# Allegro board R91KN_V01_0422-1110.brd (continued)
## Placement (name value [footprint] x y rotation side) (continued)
U202  23E22387MNG8  [BGA0_8MM10X16-100]  135.76 42.81 180 top
U401  23E22387MNG8  [BGA0_8MM10X16-100]  135.76 73.78 0 top
U402  23E22387MNG8  [BGA0_8MM10X16-100]  135.76 73.78 180 bottom
U403  V_REG_FIX_4PIN  [DPAK_4PIN]  45.04 18.44 270 top
U601  APW7065  [SO8_1_78H]  63.69 102.34 270 top
U701  APW7065  [SO8_1_78H]  149.55 101.1 90 top
U851  uPI7701U8  [SO8_THERMAL_1_75H]  46.25 44.6 90 bottom
U861  uPI7701U8  [SO8_THERMAL_1_75H]  52.44 29.69 180 bottom
U1999  XX125  [SOP65X783-14]  30.45 29.9 180 bottom
U4001  LM96163CISD  [QFN050_10_3X3]  75.65 91.9 90 top
U4050  DS4402  [TDFN14_TH]  65.88 90.24 180 top
UNK+1.8V  TP_22mil_SM_top  [TS1206]  73.75 47.15 180 bottom
UNK+1V  TP_22mil_SM_top  [TS1206]  67.35 58.3 180 bottom
UNK+5V  TP_22mil_SM_top  [TS1206]  35.05 22.05 180 bottom
UNK+MVDD  TP_22mil_SM_top  [TS1206]  150.88 75.01 180 bottom
VDDC  TP_22mil_SM_top  [TS1206]  57.55 90.9 180 bottom
Y2  27.000MHz_10PPM  [XTAL_ABLS]  65.91 28.19 180 top
Y3  27.000MHz_10PPM_30R  [XTAL_NDK_NX3225DA]  69.11 72.14 0 bottom

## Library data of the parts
B2 B5-B9 B11 B12 B71 B72 B1502 B2505 MB9 = BEAD: User Part Number: 5050005600G; alternate symbols: (SMIND1005_0_5H_BGA)
B702 = BEAD: User Part Number: 5050003200G
B800 B801 B1500 B2503 = BEAD: User Part Number: 5050007300G
B850 = BEAD: User Part Number: 5200000200G; alternate symbols: (R0805)
B4001 = BEAD: User Part Number: 5050001900G
C3-C13 C15-C19 C22-C26 C28-C33 C36-C42 C53 C57 C59 C62 C66 C71 C75 C80 C86 C87 C90 C91 C149 C156 C163-C165 C167 C193 C1051 C1054 C1601-C1614 C1999 C2530-C2538 C2541 C4071 = CAP: User Part Number: 4171010400G; alternate symbols: (CAP1005_0_55H_BGA)
C14 C715 C716 = CAP: User Part Number: 4277010600G
C20 C21 C606 C633 C706 C718 = CAP: User Part Number: 4250015400G
C27 C58 C63 C68 C77 C78 C88 C89 C130-C133 C158 C196 C629 C630 C851 C852 C856 C861 C862 C866 C4001 MC174-MC177 = CAP: User Part Number: 4217010600G
C34 C61 C64 C67 C70 C73 C79 C85 C134-C140 C143-C146 C148 C150-C155 C161 C162 C168-C173 C179-C190 C194 C195 C295 C297 C800 C801 C841 C858 C868 C1052 C1055 C1501 C1504 C1507 C2510 C2513 C2516 C2722 C4002 C4013-C4015 C4020 = CAP: User Part Number: 4172010500G; alternate symbols: (CAP1005_0_55H_BGA)
C35 C74 C120-C124 C499 C500 C1050 C4400 = CAP: User Part Number: 4170010300G; alternate symbols: (CAP1005_BGA)
C43 C44 C47 C94 C95 C854 C864 C4100 C4401 C4402 = CAP: User Part Number: 4172010400G; alternate symbols: (CAP1005_BGA,CAP1005_TRACE)
C82 C83 C92 C93 C1004-C1008 C2004-C2006 = CAP: User Part Number: 4170001200G; alternate symbols: (CAP1005_BGA)
C125-C129 C141 C142 C355-C363 C370-C377 C413 C438 C448 C463 C486-C489 C623 C725 C846 C1502 C1505 C1508 C2511 C2514 C2517 = CAP: User Part Number: 4170010400G; alternate symbols: (CAP1005_0_55H_BGA,CAP1005_0_55H_BGA_B)
C147 C174-C177 C1500 C1503 C1506 C2509 C2512 C2515 C4070 MC130-MC133 MC196 MC364-MC369 MC378-MC383 = CAP: User Part Number: 4250047500G
C300-C354 C384-C386 = CAP: User Part Number: 4170010500G; alternate symbols: (CAP1005_BGA)
C364-C369 C378-C383 C2540 = CAP: User Part Number: 4210010600G; alternate symbols: (CAP2012_1_53H_VIA)
C410 = CAP: User Part Number: *
C411 = CAP: User Part Number: *; alternate symbols: (CAP1005_BGA)
C603 C703 = CAP: User Part Number: 4210022400G
C605 C705 = CAP: User Part Number: 4240010400G
C608 = CAP: User Part Number: 4253010500G
C609 C615-C617 C619-C621 = CAP: User Part Number: 4225010600G; alternate symbols: (CAP3216_O)
C611 C624 C711 C727 = CAP: User Part Number: 4170015300G; alternate symbols: (CAP1005_BGA)
C612 C712 = CAP: User Part Number: 4170015100G; alternate symbols: (CAP1005_BGA)
C613 C713 = CAP: User Part Number: 4170039200G; alternate symbols: (CAP1005_BGA)
C625 C626 = CAP_POL#1: User Part Number: 4053082709G
C631 = CAP_POL: User Part Number: 4053027702G
C708 = CAP: User Part Number: 4171010300G; alternate symbols: (CAP1005_BGA)
C717 C719 = CAP: User Part Number: 4211047500G
C723 C724 = CAP: User Part Number: 4220010600G
C726 C729 = CAP_POL: User Part Number: 4053082700G
C728 = CAP: User Part Number: 4250039100G
C730 = CAP_POL: User Part Number: 4053010700G
C843 = CAP: User Part Number: 4173010400G; alternate symbols: (CAP1005_BGA)
C855 C865 = CAP: User Part Number: 4170033000G; alternate symbols: (CAP1005_BGA)
C1001-C1003 C2001-C2003 = CAP: User Part Number: 417008R000G; alternate symbols: (CAP1005_BGA)
C1010 = CAP: User Part Number: 4250068000G
C1011 = CAP: User Part Number: 4250010500G
C1624 = CAP: User Part Number: 4240010500G
C3600 C3608 = CAP: User Part Number: 4170068000G; alternate symbols: (CAP1005_BGA)
C4003 = CAP: User Part Number: 4170010100G; alternate symbols: (CAP1005_BGA)
C4004 = CAP: User Part Number: 4170022200G; alternate symbols: (CAP1005_BGA)
C4008 = CAP: User Part Number: 4210010500G
C4102 = CAP: User Part Number: 4213010500G
C4103 = CAP: User Part Number: 4252010500G
C4403-C4410 = CAP#1: User Part Number: 4171010400G; alternate symbols: (C0402,CAP1005_0_55H_BGA)
D601 D701 D4100 = SCHOTTKY: User Part Number: 5170005600G
D1000-D1002 D2500-D2502 D4403-D4406 = DIODE: User Part Number: 5150004000G
D1003-D1006 = DIODE: User Part Number: 5150004100G
D1600-D1603 D2503 D2504 D4401 D4402 = RCLAMP0524P: User Part Number: 5150003200G
D4000 = LED: User Part Number: 2510002300G
D4400 = DIODE_SERIES: User Part Number: 5170005400G
F400 = FUSE: User Part Number: *
F2501 = FUSE: User Part Number: 5120003100G
HS2 = HEATSINK_WVIA: User Part Number: 7120181000G
J1601 = DVI_6SH: User Part Number: 6140034304G
J2501 = 6140054500G: User Part Number: *
J4004 = CON08: User Part Number: 6020021700G
JU4001 = CON02: User Part Number: 6010007800G
L601 L701 = INDUCTOR POL: User Part Number: *
L611 = IND_POL: User Part Number: 5260054400G
L1001-L1003 L2001-L2003 = IND: User Part Number: 5260033700G
MJ1001 = VGA: User Part Number: 6052003000G
MJ2501 = 6140059200G: User Part Number: *
MPCIE1 = EDGECON_PCIE_164P: User Part Number: 614NOPN084
MR43-MR47 MR50-MR58 MR1240 MR1241 R24 R32 R43-R47 R50-R58 R63 R225 R227 R229 R230 R844 R849 R859 R862 R863 R1240 R1241 R1617 R1618 R2527 R2530 R3600 R4011 R4045 R4101 R4409 R4410 = RES: User Part Number: 3150010300G; alternate symbols: (RES1005_BGA)
MR48 MR49 R7 R35 R37-R39 R48 R49 R59 R60 R436 R4044 R4051 R4054 R4057 R4058 R4060 R4102 R4105 R4106 R4408 = RES: User Part Number: 3150010200G; alternate symbols: (RES1005_BGA)
MR70 MR71 R70 R71 R843 R845 R846 R4040 R4046 R4112 = RES: User Part Number: 3150051200G; alternate symbols: (RES1005_BGA)
MR75 R75 = RES: User Part Number: 3160182000G; alternate symbols: (RES1005_BGA)
MR850 R595 R4110 = RES: User Part Number: 3210000000G
MR858 = RES: User Part Number: 3180004100G
MR870-MR873 = RES: User Part Number: 322003R300G
MR1015-MR1019 MR1027-MR1029 R1015-R1019 = RES#1: User Part Number: 3150000000G; alternate symbols: (RES1005_BGA,RES1005_TRACE)
MR2014 MR2721 MR4076 NR75 R3 R4 R30 R36 R61 R65 R72-R74 R226 R228 R596 R597 R609 R614 R621 R709 R714 R721 R839 R856 R866 R2014 R2721 R3616 R4050 R4052 R4062 R4065 R4076-R4078 R4080 R4406 TR75 = RES: User Part Number: 3150000000G; alternate symbols: (RES1005_BGA,RES1005_TRACE)
MT200 = MOUNTING_8PINS: User Part Number: 620NOPN029
MU861 = UP7706: User Part Number: 2480086700G
NOREF#4 NOREF#13 NOREF#17 NOREF#19 NOREF#20 NOREF#24 NOREF#26 NOREF#31 NOREF#37 NOREF#41 = -: User Part Number: *
NR4000 R1005 R1008 R2005 R2008 R2701 R2703 = RES: User Part Number: 3150022200G; alternate symbols: (RES1005_BGA)
NS600 NS700 = NET_SHORT: User Part Number: 620NOPN018; alternate symbols: (NET_SHORT_0_50,NET_SHORT_SMT,NET_SHORT_SMT_0M20)
Q1 Q2 Q1200 Q1201 = MOS_N: User Part Number: 2020000600G; alternate symbols: (SOT23_3PIN_1_143H_ALT)
Q601 Q603 Q701 Q703 = MOS_N_4D_3S_TH: User Part Number: *
Q840-Q842 Q850-Q852 Q1602 Q2513 Q4006 Q4007 Q4009-Q4011 Q4013 Q4016 Q4050 Q4100 Q4401 Q4402 = NPN: User Part Number: 2021390400G
Q1601 Q2701 Q4014 = MOS_N: User Part Number: 2020002300G
Q1801 Q1802 Q1804 = MOS_N: User Part Number: *
Q1803 = NPN: User Part Number: *
Q4008 Q4101 Q4102 Q4400 = PNP: User Part Number: 2021390600G
Q4103 = NPN_2C: User Part Number: 2020030300G
R1 R2 = RES: User Part Number: 3160453200G; alternate symbols: (RES1005_BGA)
R8 = RES: User Part Number: 3160200100G; alternate symbols: (RES1005_BGA,R0402)
R9 = RES: User Part Number: 3160127100G; alternate symbols: (RES1005_BGA)
R12 R1601-R1614 R2713-R2720 R4059 = RES: User Part Number: 3160499000G; alternate symbols: (RES1005_BGA)
R13-R16 R1006 R1009 R2006 R2009 R4081 = RES: User Part Number: 3150033000G; alternate symbols: (RES1005_BGA)
R21 R76 = RES: User Part Number: 3160221000G; alternate symbols: (RES1005_BGA)
R22 = RES: User Part Number: 3160110000G; alternate symbols: (RES1005_BGA)
R23 = RES: User Part Number: 3160715000G; alternate symbols: (RES1005_BGA)
R31 = RES: User Part Number: 3160100400G; alternate symbols: (RES1005_BGA)
R33 R34 R4017 R4018 = RES: User Part Number: 3150047200G; alternate symbols: (RES1005_0_4H_BGA)
R201-R216 R611 R711 = RES: User Part Number: 3160499100G; alternate symbols: (RES1005_BGA)
R217-R220 R301-R303 = RES: User Part Number: 3160243000G; alternate symbols: (RES1005_BGA)
R221-R224 = RES: User Part Number: 3150056000G; alternate symbols: (RES1005_BGA)
R291-R294 R4001 R4002 = RES: User Part Number: 3160100000G; alternate symbols: (RES1005_0_4H_BGA)
R296 R297 = RES: User Part Number: 316051R100G; alternate symbols: (RES1005_BGA)
R298 R1500 R2500 = RES: User Part Number: 3160150000G; alternate symbols: (RES1005_BGA,RES1005_BGA_B)
R600 R622 R700 R722 = RES: User Part Number: 3230000000G
R607 R707 = RES: User Part Number: 321002R200G
R608 R616 R702 R860 R880 = RES: User Part Number: 3220000000G
R610 R1225 = RES: User Part Number: 3160787200G; alternate symbols: (RES1005_BGA)
R612 R712 = RES: User Part Number: 3160294100G; alternate symbols: (RES1005_BGA)
R613 R713 = RES: User Part Number: 3160365100G; alternate symbols: (RES1005_BGA)
R615 R715 = RES: User Part Number: 3160422200G; alternate symbols: (RES1005_BGA)
R619 = RES: User Part Number: 3210030100G
R710 = RES: User Part Number: 3160105200G
R719 R4411-R4413 = RES: User Part Number: 321001R000G
R841 = RES: User Part Number: 3160475100G; alternate symbols: (RES1005_BGA)
R850 = RES: User Part Number: 3160232100G
R851 R853 R4039 R4111 = RES: User Part Number: 3160100100G; alternate symbols: (RES1005_BGA)
R852 = RES: User Part Number: 3160113200G; alternate symbols: (RES1005_BGA)
R854 R857 R864 = RES: User Part Number: 3160100200G; alternate symbols: (RES1005_BGA)
R855 = RES: User Part Number: 3160267100G; alternate symbols: (RES1005_BGA)
R858 = RES: User Part Number: 3180002100G
R865 = RES: User Part Number: 3160130200G; alternate symbols: (RES1005_BGA)
R870-R873 = RES: User Part Number: 3180006800G
R1001-R1003 R2001-R2003 = RES: User Part Number: 316075R000G; alternate symbols: (RES1005_BGA)
R1010 R1011 = RES: User Part Number: 3150010000G; alternate symbols: (RES1005_BGA)
R1027-R1029 R2027-R2029 = RES: User Part Number: 316037R400G; alternate symbols: (RES1005_BGA)
R1226 = RES: User Part Number: 3160165300G
R1804 R1805 = RES: User Part Number: *; alternate symbols: (RES1005_BGA,R0402)
R2522 R2523 R4047 R4053 R4063 R4403 = RES: User Part Number: 3150010400G; alternate symbols: (RES1005_BGA)
R2524 R2526 R4108 = RES: User Part Number: 3150010500G; alternate symbols: (RES1005_BGA)
R3615 = RES: User Part Number: 3150068100G; alternate symbols: (RES1005_BGA)
R4038 = RES: User Part Number: 3160220100G
R4043 = RES: User Part Number: 3150047400G; alternate symbols: (RES1005_BGA)
R4055 R4061 R4404 R4405 R4407 = RES: User Part Number: 3150020300G; alternate symbols: (RES1005_BGA)
R4056 = RES: User Part Number: 315003R900G
R4070 R4071 = RES: User Part Number: 3150020100G; alternate symbols: (RES1005_BGA)
R4072 R4073 = RES: User Part Number: 3150030400G; alternate symbols: (RES1005_BGA)
R4075 = RES: User Part Number: 315001R800G; alternate symbols: (RES1005_BGA)
R4100 = RES: User Part Number: 3160261100G; alternate symbols: (RES1005_BGA)
R4103 = RES: User Part Number: 3150022300G; alternate symbols: (RES1005_BGA)
R4107 = RES: User Part Number: 3150082100G; alternate symbols: (RES1005_BGA)
R4113 = RES: User Part Number: 3150068200G; alternate symbols: (RES1005_BGA)
R4400-R4402 = RES: User Part Number: 3150047300G; alternate symbols: (RES1005_BGA)
SW4001 SW4002 = SPST: User Part Number: 5030003000G
TP58 TP59 TP91 TP94 TP97 TP101-TP123 TP500-TP503 TP1700 = TEST_POINT: User Part Number: 620NOPN000; alternate symbols: (TP07X025,TP055PRI,TP056X025,TP050,TP051X025,TP050X025,TP1_00PRI,TPVIA0_5-0_9SEC,TPVIA0_6-0_9SEC,TPVIA0_9-0_9SEC,TPVIA0_5-0_7SEC,TPSMT0_9PRI,TPSMT0_7PRI,TP089X070,TP0_127SQ_PRI,TPSMT0_7PRI)
U1 = CAICOS_DDR3: User Part Number: 215-0804000-00
U2 = SERIAL_FLASH: User Part Number: 2280007900G; alternate symbols: (SO8_1_78H_ALT)
U4 = XX08: User Part Number: 2430002900G
U12 = SL16010DCT: User Part Number: 2750013000G
U201 U202 U401 U402 = DDR3_64MX16_23E22387MNG8: alternate symbols: (BGA0_8MM10X16-100_HYNIX)
U403 = V_REG_FIX_4PIN: User Part Number: *
U601 U701 = APW7065: User Part Number: 2480059700G
U851 U861 = 2480063100G_UP7701: User Part Number: 2480063100G
U1999 = XX125: User Part Number: 2430008702G
U4001 = LM96163: User Part Number: 2480086000G
U4050 = DS4402: User Part Number: 2800006000G
UNK+1.8V UNK+1V UNK+5V UNK+MVDD VDDC = 620NOPN008: User Part Number: *
Y2 = CRYSTAL: User Part Number: 5028270002G
Y3 = CRYSTAL_4P_NC: User Part Number: 502G270000G

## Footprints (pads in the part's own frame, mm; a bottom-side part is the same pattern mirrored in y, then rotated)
BGA0_8MM10X16-100
  round 0.356 smd: (-4,6) (-4,-6) (4,6) (4,-6) A1(-3.2,6) A2(-2.4,6) A3(-1.6,6) A7(1.6,6) A8(2.4,6) A9(3.2,6) B1(-3.2,5.2) B2(-2.4,5.2) B3(-1.6,5.2) B7(1.6,5.2) B8(2.4,5.2) B9(3.2,5.2) C1(-3.2,4.4) C2(-2.4,4.4) C3(-1.6,4.4) C7(1.6,4.4) C8(2.4,4.4) C9(3.2,4.4) D1(-3.2,3.6) D2(-2.4,3.6) D3(-1.6,3.6) D7(1.6,3.6) D8(2.4,3.6) D9(3.2,3.6) E1(-3.2,2.8) E2(-2.4,2.8) E3(-1.6,2.8) E7(1.6,2.8) E8(2.4,2.8) E9(3.2,2.8) F1(-3.2,2) F2(-2.4,2) F3(-1.6,2) F7(1.6,2) F8(2.4,2) F9(3.2,2) G1(-3.2,1.2) G2(-2.4,1.2) G3(-1.6,1.2) G7(1.6,1.2) G8(2.4,1.2) G9(3.2,1.2) H1(-3.2,0.4) H2(-2.4,0.4) H3(-1.6,0.4) H7(1.6,0.4) H8(2.4,0.4) H9(3.2,0.4) J1(-3.2,-0.4) J2(-2.4,-0.4) J3(-1.6,-0.4) J7(1.6,-0.4) J8(2.4,-0.4) J9(3.2,-0.4) K1(-3.2,-1.2) K2(-2.4,-1.2) K3(-1.6,-1.2) K7(1.6,-1.2) K8(2.4,-1.2) K9(3.2,-1.2) L1(-3.2,-2) L2(-2.4,-2) L3(-1.6,-2) L7(1.6,-2) L8(2.4,-2) L9(3.2,-2) M1(-3.2,-2.8) M2(-2.4,-2.8) M3(-1.6,-2.8) M7(1.6,-2.8) M8(2.4,-2.8) M9(3.2,-2.8) N1(-3.2,-3.6) N2(-2.4,-3.6) N3(-1.6,-3.6) N7(1.6,-3.6) N8(2.4,-3.6) N9(3.2,-3.6) P1(-3.2,-4.4) P2(-2.4,-4.4) P3(-1.6,-4.4) P7(1.6,-4.4) P8(2.4,-4.4) P9(3.2,-4.4) R1(-3.2,-5.2) R2(-2.4,-5.2) R3(-1.6,-5.2) R7(1.6,-5.2) R8(2.4,-5.2) R9(3.2,-5.2) T1(-3.2,-6) T2(-2.4,-6) T3(-1.6,-6) T7(1.6,-6) T8(2.4,-6) T9(3.2,-6)
BGA0_8X1_0MM23X23-631
  round 0.406 smd: A3(-10,10.8) A30(10,10.8) A32(10.8,10.8) AB7(-7.6,-4.2) AB8(-6.8,-4.2) AB9(-6,-4.2) AB10(-5.2,-4.2) AB23(5.2,-4.2) AB24(6,-4.2) AB25(6.8,-4.2) AB26(7.6,-4.2) AC11(-4.2,-5.2) AC13(-3,-5.2) AC14(-1.8,-5.2) AC16(-0.6,-5.2) AC17(0.6,-5.2) AC19(1.8,-5.2) AC20(3,-5.2) AC22(4.2,-5.2) AD11(-4.2,-6) AD13(-3,-6) AD14(-1.8,-6) AD16(-0.6,-6) AD17(0.6,-6) AD19(1.8,-6) AD20(3,-6) AD22(4.2,-6) AE11(-4.2,-6.8) AE13(-3,-6.8) AE14(-1.8,-6.8) AE16(-0.6,-6.8) AE17(0.6,-6.8) AE19(1.8,-6.8) AE20(3,-6.8) AE22(4.2,-6.8) AF11(-4.2,-7.6) AF13(-3,-7.6) AF14(-1.8,-7.6) AF16(-0.6,-7.6) AF17(0.6,-7.6) AF19(1.8,-7.6) AF20(3,-7.6) AF22(4.2,-7.6) AK1(-10.8,-10) AK3(-10,-10) AK30(10,-10) AK32(10.8,-10) AM1(-10.8,-10.8) AM3(-10,-10.8) AM30(10,-10.8) AM32(10.8,-10.8) C1(-10.8,10) C3(-10,10) C30(10,10) C32(10.8,10) G11(-4.2,7.6) G13(-3,7.6) G14(-1.8,7.6) G16(-0.6,7.6) G17(0.6,7.6) G19(1.8,7.6) G20(3,7.6) G22(4.2,7.6) H11(-4.2,6.8) H13(-3,6.8) H14(-1.8,6.8) H16(-0.6,6.8) H17(0.6,6.8) H19(1.8,6.8) H20(3,6.8) H22(4.2,6.8) J11(-4.2,6) J13(-3,6) J14(-1.8,6) J16(-0.6,6) J17(0.6,6) J19(1.8,6) J20(3,6) J22(4.2,6) K11(-4.2,5.2) K13(-3,5.2) K14(-1.8,5.2) K16(-0.6,5.2) K17(0.6,5.2) K19(1.8,5.2) K20(3,5.2) K22(4.2,5.2) L7(-7.6,4.2) L8(-6.8,4.2) L9(-6,4.2) L10(-5.2,4.2) L23(5.2,4.2) L24(6,4.2) L25(6.8,4.2) L26(7.6,4.2) N7(-7.6,3) N8(-6.8,3) N9(-6,3) N10(-5.2,3) N23(5.2,3) N24(6,3) N25(6.8,3) N26(7.6,3) P7(-7.6,1.8) P8(-6.8,1.8) P9(-6,1.8) P10(-5.2,1.8) P23(5.2,1.8) P24(6,1.8) P25(6.8,1.8) P26(7.6,1.8) T7(-7.6,0.6) T8(-6.8,0.6) T9(-6,0.6) T10(-5.2,0.6) T23(5.2,0.6) T24(6,0.6) T25(6.8,0.6) T26(7.6,0.6) U7(-7.6,-0.6) U8(-6.8,-0.6) U9(-6,-0.6) U10(-5.2,-0.6) U23(5.2,-0.6) U24(6,-0.6) U25(6.8,-0.6) U26(7.6,-0.6) W7(-7.6,-1.8) W8(-6.8,-1.8) W9(-6,-1.8) W10(-5.2,-1.8) W23(5.2,-1.8) W24(6,-1.8) W25(6.8,-1.8) W26(7.6,-1.8) Y7(-7.6,-3) Y8(-6.8,-3) Y9(-6,-3) Y10(-5.2,-3) Y23(5.2,-3) Y24(6,-3) Y25(6.8,-3) Y26(7.6,-3)
  round 0.3 smd: A5(-9.2,10.8) A7(-7.6,10.8) A9(-6,10.8) A11(-4.4,10.8) A13(-2.8,10.8) A15(-1.2,10.8) A17(0.4,10.8) A19(2,10.8) A21(3.6,10.8) A23(5.2,10.8) A25(6.8,10.8) A27(8.4,10.8) A28(9.2,10.8) AA1(-10.8,-3.6) AA3(-10,-3.6) AA5(-9.2,-3.6) AA6(-8.4,-3.6) AA27(8.4,-3.6) AA29(9.6,-3.6) AA31(10.4,-3.6) AB2(-10.4,-4.4) AB4(-9.6,-4.4) AB6(-8.4,-4.4) AB27(8.4,-4.4) AB28(9.2,-4.4) AB30(10,-4.4) AB32(10.8,-4.4) AC1(-10.8,-5.2) AC3(-10,-5.2) AC5(-9.2,-5.2) AC6(-8.4,-5.2) AC7(-7.6,-5.2) AC8(-6.8,-5.2) AC9(-6,-5.2) AC10(-5.2,-5.2) AC23(5.2,-5.2) AC24(6,-5.2) AC25(6.8,-5.2) AC26(7.6,-5.2) AC27(8.4,-5.2) AC29(9.6,-5.2) AC31(10.4,-5.2) AD2(-10.4,-6) AD4(-9.6,-6) AD6(-8.4,-6) AD7(-7.6,-6) AD8(-6.8,-6) AD9(-6,-6) AD10(-5.2,-6) AD23(5.2,-6) AD24(6,-6) AD25(6.8,-6) AD26(7.6,-6) AD27(8.4,-6) AD28(9.2,-6) AD30(10,-6) AD32(10.8,-6) AE1(-10.8,-6.8) AE3(-10,-6.8) AE5(-9.2,-6.8) AE6(-8.4,-6.8) AE7(-7.6,-6.8) AE8(-6.8,-6.8) AE9(-6,-6.8) AE10(-5.2,-6.8) AE23(5.2,-6.8) AE24(6,-6.8) AE25(6.8,-6.8) AE26(7.6,-6.8) AE27(8.4,-6.8) AE29(9.6,-6.8) AE31(10.4,-6.8) AF2(-10.4,-7.6) AF4(-9.6,-7.6) AF6(-8.4,-7.6) AF7(-7.6,-7.6) AF8(-6.8,-7.6) AF9(-6,-7.6) AF10(-5.2,-7.6) AF23(5.2,-7.6) AF24(6,-7.6) AF25(6.8,-7.6) AF26(7.6,-7.6) AF27(8.4,-7.6) AF28(9.2,-7.6) AF30(10,-7.6) AF32(10.8,-7.6) AG1(-10.8,-8.4) AG3(-10,-8.4) AG5(-9.2,-8.4) AG6(-8.4,-8.4) AG7(-7.6,-8.4) AG8(-6.8,-8.4) AG9(-6,-8.4) AG10(-5.2,-8.4) AG11(-4.4,-8.4) AG12(-3.6,-8.4) AG13(-2.8,-8.4) AG14(-2,-8.4) AG15(-1.2,-8.4) AG16(-0.4,-8.4) AG17(0.4,-8.4) AG18(1.2,-8.4) AG19(2,-8.4) AG20(2.8,-8.4) AG21(3.6,-8.4) AG22(4.4,-8.4) AG23(5.2,-8.4) AG24(6,-8.4) AG25(6.8,-8.4) AG26(7.6,-8.4) AG27(8.4,-8.4) AG29(9.6,-8.4) AG31(10.4,-8.4) AH1(-10.8,-9.2) AH3(-10,-9.2) AH5(-9.2,-9.2) AH6(-8.4,-9.2) AH8(-6.8,-9.2) AH10(-5.2,-9.2) AH12(-3.6,-9.2) AH14(-2,-9.2) AH16(-0.4,-9.2) AH18(1.2,-9.2) AH20(2.8,-9.2) AH22(4.4,-9.2) AH24(6,-9.2) AH26(7.6,-9.2) AH28(9.2,-9.2) AH30(10,-9.2) AH32(10.8,-9.2) AJ7(-7.6,-9.6) AJ9(-6,-9.6) AJ11(-4.4,-9.6) AJ13(-2.8,-9.6) AJ15(-1.2,-9.6) AJ17(0.4,-9.6) AJ19(2,-9.6) AJ21(3.6,-9.6) AJ23(5.2,-9.6) AJ25(6.8,-9.6) AJ27(8.4,-9.6) AK5(-9.2,-10) AK6(-8.4,-10) AK8(-6.8,-10) AK10(-5.2,-10) AK12(-3.6,-10) AK14(-2,-10) AK16(-0.4,-10) AK18(1.2,-10) AK20(2.8,-10) AK22(4.4,-10) AK24(6,-10) AK26(7.6,-10) AK28(9.2,-10) AL7(-7.6,-10.4) AL9(-6,-10.4) AL11(-4.4,-10.4) AL13(-2.8,-10.4) AL15(-1.2,-10.4) AL17(0.4,-10.4) AL19(2,-10.4) AL21(3.6,-10.4) AL23(5.2,-10.4) AL25(6.8,-10.4) AL27(8.4,-10.4) AM5(-9.2,-10.8) AM6(-8.4,-10.8) AM8(-6.8,-10.8) AM10(-5.2,-10.8) AM12(-3.6,-10.8) AM14(-2,-10.8) AM16(-0.4,-10.8) AM18(1.2,-10.8) AM20(2.8,-10.8) AM22(4.4,-10.8) AM24(6,-10.8) AM26(7.6,-10.8) AM28(9.2,-10.8) B6(-8.4,10.4) B8(-6.8,10.4) B10(-5.2,10.4) B12(-3.6,10.4) B14(-2,10.4) B16(-0.4,10.4) B18(1.2,10.4) B20(2.8,10.4) B22(4.4,10.4) B24(6,10.4) B26(7.6,10.4) C5(-9.2,10) C7(-7.6,10) C9(-6,10) C11(-4.4,10) C13(-2.8,10) C15(-1.2,10) C17(0.4,10) C19(2,10) C21(3.6,10) C23(5.2,10) C25(6.8,10) C27(8.4,10) C28(9.2,10) D6(-8.4,9.6) D8(-6.8,9.6) D10(-5.2,9.6) D12(-3.6,9.6) D14(-2,9.6) D16(-0.4,9.6) D18(1.2,9.6) D20(2.8,9.6) D22(4.4,9.6) D24(6,9.6) D26(7.6,9.6) E1(-10.8,9.2) E3(-10,9.2) E5(-9.2,9.2) E7(-7.6,9.2) E9(-6,9.2) E11(-4.4,9.2) E13(-2.8,9.2) E15(-1.2,9.2) E17(0.4,9.2) E19(2,9.2) E21(3.6,9.2) E23(5.2,9.2) E25(6.8,9.2) E27(8.4,9.2) E28(9.2,9.2) E30(10,9.2) E32(10.8,9.2) F2(-10.4,8.4) F4(-9.6,8.4) F6(-8.4,8.4) F7(-7.6,8.4) F8(-6.8,8.4) F9(-6,8.4) F10(-5.2,8.4) F11(-4.4,8.4) F12(-3.6,8.4) F13(-2.8,8.4) F14(-2,8.4) F15(-1.2,8.4) F16(-0.4,8.4) F17(0.4,8.4) F18(1.2,8.4) F19(2,8.4) F20(2.8,8.4) F21(3.6,8.4) F22(4.4,8.4) F23(5.2,8.4) F24(6,8.4) F25(6.8,8.4) F26(7.6,8.4) F27(8.4,8.4) F28(9.2,8.4) F30(10,8.4) F32(10.8,8.4) G1(-10.8,7.6) G3(-10,7.6) G5(-9.2,7.6) G6(-8.4,7.6) G7(-7.6,7.6) G8(-6.8,7.6) G9(-6,7.6) G10(-5.2,7.6) G23(5.2,7.6) G24(6,7.6) G25(6.8,7.6) G26(7.6,7.6) G27(8.4,7.6) G29(9.6,7.6) G31(10.4,7.6) H2(-10.4,6.8) H4(-9.6,6.8) H6(-8.4,6.8) H7(-7.6,6.8) H8(-6.8,6.8) H9(-6,6.8) H10(-5.2,6.8) H23(5.2,6.8) H24(6,6.8) H25(6.8,6.8) H26(7.6,6.8) H27(8.4,6.8) H28(9.2,6.8) H30(10,6.8) H32(10.8,6.8) J1(-10.8,6) J3(-10,6) J5(-9.2,6) J6(-8.4,6) J7(-7.6,6) J8(-6.8,6) J9(-6,6) J10(-5.2,6) J23(5.2,6) J24(6,6) J25(6.8,6) J26(7.6,6) J27(8.4,6) J29(9.6,6) J31(10.4,6) K2(-10.4,5.2) K4(-9.6,5.2) K6(-8.4,5.2) K7(-7.6,5.2) K8(-6.8,5.2) K9(-6,5.2) K10(-5.2,5.2) K23(5.2,5.2) K24(6,5.2) K25(6.8,5.2) K26(7.6,5.2) K27(8.4,5.2) K28(9.2,5.2) K30(10,5.2) K32(10.8,5.2) L1(-10.8,4.4) L3(-10,4.4) L5(-9.2,4.4) L6(-8.4,4.4) L27(8.4,4.4) L29(9.6,4.4) L31(10.4,4.4) M2(-10.4,3.6) M4(-9.6,3.6) M6(-8.4,3.6) M27(8.4,3.6) M28(9.2,3.6) M30(10,3.6) M32(10.8,3.6) N1(-10.8,2.8) N3(-10,2.8) N5(-9.2,2.8) N6(-8.4,2.8) N27(8.4,2.8) N29(9.6,2.8) N31(10.4,2.8) P2(-10.4,2) P4(-9.6,2) P6(-8.4,2) P27(8.4,2) P28(9.2,2) P30(10,2) P32(10.8,2) R1(-10.8,1.2) R3(-10,1.2) R5(-9.2,1.2) R6(-8.4,1.2) R27(8.4,1.2) R29(9.6,1.2) R31(10.4,1.2) T2(-10.4,0.4) T4(-9.6,0.4) T6(-8.4,0.4) T27(8.4,0.4) T28(9.2,0.4) T30(10,0.4) T32(10.8,0.4) U1(-10.8,-0.4) U3(-10,-0.4) U5(-9.2,-0.4) U6(-8.4,-0.4) U27(8.4,-0.4) U29(9.6,-0.4) U31(10.4,-0.4) V2(-10.4,-1.2) V4(-9.6,-1.2) V6(-8.4,-1.2) V27(8.4,-1.2) V28(9.2,-1.2) V30(10,-1.2) V32(10.8,-1.2) W1(-10.8,-2) W3(-10,-2) W5(-9.2,-2) W6(-8.4,-2) W27(8.4,-2) W29(9.6,-2) W31(10.4,-2) Y2(-10.4,-2.8) Y4(-9.6,-2.8) Y6(-8.4,-2.8) Y27(8.4,-2.8) Y28(9.2,-2.8) Y30(10,-2.8) Y32(10.8,-2.8)
  round 0.5 smd: AA11(-4.4,-3.4) AA12(-3.4,-3.4) AA13(-2.4,-3.4) AA15(-1.4,-3.4) AA16(-0.4,-3.4) AA17(0.4,-3.4) AA18(1.4,-3.4) AA20(2.4,-3.4) AA21(3.4,-3.4) AA22(4.4,-3.4) AB11(-4.4,-4.4) AB12(-3.4,-4.4) AB13(-2.4,-4.4) AB15(-1.4,-4.4) AB16(-0.4,-4.4) AB17(0.4,-4.4) AB18(1.4,-4.4) AB20(2.4,-4.4) AB21(3.4,-4.4) AB22(4.4,-4.4) L11(-4.4,4.4) L12(-3.4,4.4) L13(-2.4,4.4) L15(-1.4,4.4) L16(-0.4,4.4) L17(0.4,4.4) L18(1.4,4.4) L20(2.4,4.4) L21(3.4,4.4) L22(4.4,4.4) M11(-4.4,3.4) M12(-3.4,3.4) M13(-2.4,3.4) M15(-1.4,3.4) M16(-0.4,3.4) M17(0.4,3.4) M18(1.4,3.4) M20(2.4,3.4) M21(3.4,3.4) M22(4.4,3.4) N11(-4.4,2.4) N12(-3.4,2.4) N13(-2.4,2.4) N15(-1.4,2.4) N16(-0.4,2.4) N17(0.4,2.4) N18(1.4,2.4) N20(2.4,2.4) N21(3.4,2.4) N22(4.4,2.4) R11(-4.4,1.4) R12(-3.4,1.4) R13(-2.4,1.4) R15(-1.4,1.4) R16(-0.4,1.4) R17(0.4,1.4) R18(1.4,1.4) R20(2.4,1.4) R21(3.4,1.4) R22(4.4,1.4) T11(-4.4,0.4) T12(-3.4,0.4) T13(-2.4,0.4) T15(-1.4,0.4) T16(-0.4,0.4) T17(0.4,0.4) T18(1.4,0.4) T20(2.4,0.4) T21(3.4,0.4) T22(4.4,0.4) U11(-4.4,-0.4) U12(-3.4,-0.4) U13(-2.4,-0.4) U15(-1.4,-0.4) U16(-0.4,-0.4) U17(0.4,-0.4) U18(1.4,-0.4) U20(2.4,-0.4) U21(3.4,-0.4) U22(4.4,-0.4) V11(-4.4,-1.4) V12(-3.4,-1.4) V13(-2.4,-1.4) V15(-1.4,-1.4) V16(-0.4,-1.4) V17(0.4,-1.4) V18(1.4,-1.4) V20(2.4,-1.4) V21(3.4,-1.4) V22(4.4,-1.4) Y11(-4.4,-2.4) Y12(-3.4,-2.4) Y13(-2.4,-2.4) Y15(-1.4,-2.4) Y16(-0.4,-2.4) Y17(0.4,-2.4) Y18(1.4,-2.4) Y20(2.4,-2.4) Y21(3.4,-2.4) Y22(4.4,-2.4)
CAP254X635_8_26H
  rect 1.397x1.397 hole 1: 1(-1.27,0)
  round 1.397 hole 1: 2(1.27,0)
CAP1005
  custom 0.138x0.138 smd: 1(0,0.493) 2(0,-0.493)
CAP1005_0_55H
  custom 0.138x0.138 smd: 1(0,0.493) 2(0,-0.493)
CAP1608
  custom 0.225x0.225 smd: 1(0,0.787) 2(0,-0.787)
CAP1608_0_89H
  custom 0.225x0.225 smd: 1(0,0.787) 2(0,-0.787)
CAP1608_2012_1_40H
  custom 0.305x0.305 smd: 1(0,0.914) 2(0,-0.914)
CAP1608_2012_1_53H
  custom 0.305x0.305 smd: 1(0,0.914) 2(0,-0.914)
CAP1608_2012POL
  custom 0.305x0.305 smd: 1(0,0.914) 2(0,-0.914)
CAP3216_1_80H
  custom 0.35x0.35 smd: 1(0,1.448) 2(0,-1.448)
CAP3216_1_524H
  custom 0.35x0.35 smd: 1(0,1.448) 2(0,-1.448)
CAP_E_6M3X9M0_P2M5
  rect 1.651x1.651 hole 1: 1(-1.25,0)
  round 1.651 hole 1: 2(1.25,0)
CAP_E_6M3X12M5_P2M5
  rect 1.9x1.9 hole 1.2: 1(-1.25,0)
  round 1.9 hole 1.1: 2(1.25,0)
CON_2X4_SAMTEC_CLP_NOALIGN
  custom 0.188x0.188 smd: 1(1.905,-1.615) 2(1.905,1.615) 3(0.635,-1.615) 4(0.635,1.615) 5(-0.635,-1.615) 6(-0.635,1.615) 7(-1.905,-1.615) 8(-1.905,1.615)
CON_DISPLAYPORT_ASTRON_R6890020
  round 1.5 hole 1.5 unplated: (0,3.28)
  oval 0.27x2.6 smd: 1(5.5,13.56) 2(5,13.56) 3(4.5,13.56) 4(4,13.56) 5(3.5,13.56) 6(3,13.56) 7(2.5,13.56) 8(2,13.56) 9(1.5,13.56) 10(1,13.56) 11(0.5,13.56) 12(0,13.56) 13(-0.5,13.56) 14(-1,13.56) 15(-1.5,13.56) 16(-2,13.56) 17(-2.5,13.56) 18(-3,13.56) 19(-3.5,13.56) 20(-4,13.56)
  oval 2x3.8 hole 1x2.8: G1(-8.2,10.96) G3(8.2,10.96)
  oval 2x3.2 hole 1x2.2: G2(-8.2,4.18) G4(8.2,4.18)
CON_FOXCONN_PLASTRON_DI0B1-G-H0-LF-HF
  round 1 hole 1.95 unplated: (-9.525,2.542) (9.525,2.542)
  round 1.397 hole 0.9: 1(-9.525,9.652) 2(-7.62,9.652) 3(-5.715,9.652) 4(-3.81,9.652) 5(-1.905,9.652) 6(0,9.652) 7(1.905,9.652) 8(3.81,9.652) 9(-9.525,7.747) 10(-7.62,7.747) 11(-5.715,7.747) 12(-3.81,7.747) 13(-1.905,7.747) 14(0,7.747) 15(1.905,7.747) 16(3.81,7.747) 17(-9.525,5.842) 18(-7.62,5.842) 19(-5.715,5.842) 20(-3.81,5.842) 21(-1.905,5.842) 22(0,5.842) 23(1.905,5.842) 24(3.81,5.842)
  oval 3x5.5 hole 2x4.5: 25(15.365,4.572) 26(-15.365,4.572)
  oval 1.9x2.1 hole 1.4x1.6: 27(-3.815,11.9) 28(3.185,11.9) 29(13.5,11.9) 30(-13.5,11.9)
  round 1.143 hole 0.65: C1(6.985,9.019) C2(9.525,9.019) C3(6.985,6.479) C4(9.525,6.479) C5(8.255,10.292) C6(8.255,5.212)
CON_HDMI_RT_MOLEX500254
  rect 0.28x2.6 smd: 1(4.5,10.31) 2(4,10.31) 3(3.5,10.31) 4(3,10.31) 5(2.5,10.31) 6(2,10.31) 7(1.5,10.31) 8(1,10.31) 9(0.5,10.31) 10(0,10.31) 11(-0.5,10.31) 12(-1,10.31) 13(-1.5,10.31) 14(-2,10.31) 15(-2.5,10.31) 16(-3,10.31) 17(-3.5,10.31) 18(-4,10.31) 19(-4.5,10.31)
  oval 1.8x3.6 hole 0.289: 20(7.25,9.55) 21(-7.25,9.55)
  oval 1.8x3 hole 0.259: 22(-7.25,3.6) 23(7.25,3.59)
CON_WIESON_31796219
  round 0.64 hole 1.95 unplated: (-9.525,2.54) (9.525,2.54)
  round 0.965 hole 0.6: 1(3.81,2.186) 2(1.524,3.186) 3(-0.762,2.186) 4(-3.048,3.186) 5(-5.334,2.186) 6(5.334,2.186) 7(3.048,3.186) 8(0.762,2.186) 9(-1.524,3.186) 10(-3.81,2.186) 11(4.572,3.186) 12(2.286,2.186) 13(0,3.186) 14(-2.286,2.186) 15(-4.572,3.186)
  oval 3.7x1.7 hole 3x1: 16(12.51,2.786) 17(-12.51,2.786)
DIO_CLAMP_SLP2510P8
  rect 0.2x0.675 smd: 1(-1,-0.438) 2(-0.5,-0.438) 4(0.5,-0.438) 5(1,-0.438) 6(1,0.438) 7(0.5,0.438) 9(-0.5,0.438) 10(-1,0.438)
  rect 0.4x0.675 smd: 3(0,-0.438) 8(0,0.438)
DIO_SML-010LTT87
  custom 0.45x0.45 smd: 1(0,1.27) 2(0,-1.27)
DIOSOD_523
  rect 0.508x1.016 smd: 1(0,1.016) 2(0,-1.016)
DPAK_4PIN
  rect 1.65x3.05 smd: 1(2.286,2.794) 2(0,2.794) 3(-2.286,2.794)
  rect 6.99x5.97 smd: 4(0,-4.191)
EDGECON_PCI_EXPRESS_16
  round 0.55 hole 0.25: (-13,-1.5) (73,-1.5)
  rect 0.7x3.2 smd: A1(-11.5,4) B81(70.5,4)
  rect 0.7x4.2 smd: A2(-10.5,3.5) A3(-9.5,3.5) A4(-8.5,3.5) A5(-7.5,3.5) A6(-6.5,3.5) A7(-5.5,3.5) A8(-4.5,3.5) A9(-3.5,3.5) A10(-2.5,3.5) A11(-1.5,3.5) A12(1.5,3.5) A13(2.5,3.5) A14(3.5,3.5) A15(4.5,3.5) A16(5.5,3.5) A17(6.5,3.5) A18(7.5,3.5) A19(8.5,3.5) A20(9.5,3.5) A21(10.5,3.5) A22(11.5,3.5) A23(12.5,3.5) A24(13.5,3.5) A25(14.5,3.5) A26(15.5,3.5) A27(16.5,3.5) A28(17.5,3.5) A29(18.5,3.5) A30(19.5,3.5) A31(20.5,3.5) A32(21.5,3.5) A33(22.5,3.5) A34(23.5,3.5) A35(24.5,3.5) A36(25.5,3.5) A37(26.5,3.5) A38(27.5,3.5) A39(28.5,3.5) A40(29.5,3.5) A41(30.5,3.5) A42(31.5,3.5) A43(32.5,3.5) A44(33.5,3.5) A45(34.5,3.5) A46(35.5,3.5) A47(36.5,3.5) A48(37.5,3.5) A49(38.5,3.5) A50(39.5,3.5) A51(40.5,3.5) A52(41.5,3.5) A53(42.5,3.5) A54(43.5,3.5) A55(44.5,3.5) A56(45.5,3.5) A57(46.5,3.5) A58(47.5,3.5) A59(48.5,3.5) A60(49.5,3.5) A61(50.5,3.5) A62(51.5,3.5) A63(52.5,3.5) A64(53.5,3.5) A65(54.5,3.5) A66(55.5,3.5) A67(56.5,3.5) A68(57.5,3.5) A69(58.5,3.5) A70(59.5,3.5) A71(60.5,3.5) A72(61.5,3.5) A73(62.5,3.5) A74(63.5,3.5) A75(64.5,3.5) A76(65.5,3.5) A77(66.5,3.5) A78(67.5,3.5) A79(68.5,3.5) A80(69.5,3.5) A81(70.5,3.5) A82(71.5,3.5) B1(-11.5,3.5) B2(-10.5,3.5) B3(-9.5,3.5) B4(-8.5,3.5) B5(-7.5,3.5) B6(-6.5,3.5) B7(-5.5,3.5) B8(-4.5,3.5) B9(-3.5,3.5) B10(-2.5,3.5) B11(-1.5,3.5) B12(1.5,3.5) B13(2.5,3.5) B14(3.5,3.5) B15(4.5,3.5) B16(5.5,3.5) B17(6.5,3.5) B18(7.5,3.5) B19(8.5,3.5) B20(9.5,3.5) B21(10.5,3.5) B22(11.5,3.5) B23(12.5,3.5) B24(13.5,3.5) B25(14.5,3.5) B26(15.5,3.5) B27(16.5,3.5) B28(17.5,3.5) B29(18.5,3.5) B30(19.5,3.5) B31(20.5,3.5) B32(21.5,3.5) B33(22.5,3.5) B34(23.5,3.5) B35(24.5,3.5) B36(25.5,3.5) B37(26.5,3.5) B38(27.5,3.5) B39(28.5,3.5) B40(29.5,3.5) B41(30.5,3.5) B42(31.5,3.5) B43(32.5,3.5) B44(33.5,3.5) B45(34.5,3.5) B46(35.5,3.5) B47(36.5,3.5) B48(37.5,3.5) B49(38.5,3.5) B50(39.5,3.5) B51(40.5,3.5) B52(41.5,3.5) B53(42.5,3.5) B54(43.5,3.5) B55(44.5,3.5) B56(45.5,3.5) B57(46.5,3.5) B58(47.5,3.5) B59(48.5,3.5) B60(49.5,3.5) B61(50.5,3.5) B62(51.5,3.5) B63(52.5,3.5) B64(53.5,3.5) B65(54.5,3.5) B66(55.5,3.5) B67(56.5,3.5) B68(57.5,3.5) B69(58.5,3.5) B70(59.5,3.5) B71(60.5,3.5) B72(61.5,3.5) B73(62.5,3.5) B74(63.5,3.5) B75(64.5,3.5) B76(65.5,3.5) B77(66.5,3.5) B78(67.5,3.5) B79(68.5,3.5) B80(69.5,3.5) B82(71.5,3.5)
HD2MM1X2_KEY
  rect 1.397x1.397 hole 1: 1(0,0)
  round 1.397 hole 1: 2(2,0)
HS_7120181000G
  round 3.175 hole 3.175 unplated: (-21.6,21.6) (-21.6,-21.6) (21.6,21.6) (21.6,-21.6)
  round 0.55 hole 0.25: 1(-21.517,23.942) 2(-19.706,23.159) 3(-19.157,21.654) 4(-19.859,19.979) 5(-21.508,19.234) 6(-23.133,19.843) 7(-23.928,21.544) 8(-23.276,23.109) 9(19.898,23.207) 10(21.573,23.935) 11(23.367,23.123) 12(19.273,21.583) 13(23.959,21.549) 14(21.709,19.232) 15(20.051,19.841) 16(23.181,19.892) 17(19.88,-20.014) 18(21.572,-19.219) 19(21.657,-23.906) 20(19.271,-21.435) 21(23.991,-21.452) 22(23.45,-20.099) 23(19.931,-23.212) 24(23.247,-23.127) 25(-21.637,-19.26) 26(-19.742,-20.106) 27(-19.167,-21.68) 28(-20.013,-23.253) 29(-21.535,-23.93) 30(-23.109,-23.338) 31(-23.921,-21.612) 32(-23.227,-19.971)
IND_3216_4515
  custom 0.45x0.45 smd: 1(0,1.714) 2(0,-1.714)
IND_GUORUI_SCD0504T
  rect 2.5x5.2 smd: 1(-2.05,0) 2(2.05,0)
IND_TRIO_LD-10AM10003
  round 3.302 hole 2.15: 1(-2.25,-3.25) 2(2.25,3.25)
MTG3_4_8VIAS
  round 3 hole 3.4 unplated: (0,0)
  round 0.55 hole 0.25: 1(0,2.475) 2(1.75,1.75) 3(2.475,0) 4(1.75,-1.75) 5(0,-2.475) 6(-1.75,-1.75) 7(-2.475,0) 8(-1.75,1.75)
NET_SHORT
  round 0.55 hole 0.25: 1(0,0)
  round 0.127 smd: 2(0.2,0)
QFN050_10_3X3
  custom 0.058x0.058 smd: 1(-1.377,1) 2(-1.377,0.5) 3(-1.377,0) 4(-1.377,-0.5) 5(-1.377,-1) 6(1.377,-1) 7(1.377,-0.5) 8(1.377,0) 9(1.377,0.5) 10(1.377,1)
  round 0.275 smd: 11(0,0)
RES1005
  custom 0.138x0.138 smd: 1(0,0.493) 2(0,-0.493)
RES1005_0_4H
  custom 0.138x0.138 smd: 1(0,0.493) 2(0,-0.493)
RES1608
  custom 0.225x0.225 smd: 1(0,0.787) 2(0,-0.787)
RES1608_2012
  custom 0.305x0.305 smd: 1(0,0.914) 2(0,-0.914)
RES1608_2012_1_1H
  custom 0.305x0.305 smd: 1(0,0.914) 2(0,-0.914)
RES3216
  custom 0.35x0.35 smd: 1(0,1.448) 2(0,-1.448)
RES3216_1_3H
  custom 0.35x0.35 smd: 1(0,1.448) 2(0,-1.448)
RES3225_0_7H
  rect 2.794x1.397 smd: 1(0,1.448) 2(0,-1.448)
SMIND1005_0_5H
  custom 0.138x0.138 smd: 1(0,0.493) 2(0,-0.493)
SMIND_TSSLP-2-1_0_40H
  rect 0.65x0.35 smd: 1(0,0.325) 2(0,-0.325)
SO8_1_78H
  oval 0.64x1.9 smd: 1(-1.905,-2.845) 2(-0.635,-2.845) 3(0.635,-2.845) 4(1.905,-2.845) 5(1.905,2.87) 6(0.635,2.87) 7(-0.635,2.87) 8(-1.905,2.87)
SO8_POWERPAK_1_1H
  rect 0.76x1.6 smd: 1(-1.905,-3.175) 2(-0.635,-3.175) 3(0.635,-3.175) 4(1.905,-3.175) 5(1.905,3.17) 6(0.635,3.17) 7(-0.635,3.17) 8(-1.905,3.17)
  custom 0.869x0.869 smd: 9(0,0)
SO8_THERMAL_1_75H
  oval 0.64x1.9 smd: 1(-1.905,-2.845) 2(-0.635,-2.845) 3(0.635,-2.845) 4(1.905,-2.845) 5(1.905,2.87) 6(0.635,2.87) 7(-0.635,2.87) 8(-1.905,2.87)
  rect 4.1x2.8 smd: 9(0,0)
SOP65X783-14
  oval 0.4x1.8 smd: 1(-1.95,-2.97) 2(-1.3,-2.97) 3(-0.65,-2.97) 4(0,-2.97) 5(0.65,-2.97) 6(1.3,-2.97) 7(1.95,-2.97) 8(1.95,2.97) 9(1.3,2.97) 10(0.65,2.97) 11(0,2.97) 12(-0.65,2.97) 13(-1.3,2.97) 14(-1.95,2.97)
SOT23_3PIN
  custom 0.16x0.16 smd: 1(-0.94,-1.143) 2(0.94,-1.143) 3(0,1.143)
SOT23_3PIN_1_1H
  custom 0.16x0.16 smd: 1(-0.94,-1.143) 2(0.94,-1.143) 3(0,1.143)
SOT223
  rect 1.524x2.032 smd: 1(2.286,3.175) 2(0,3.175) 3(-2.286,3.175)
  rect 3.81x2.032 smd: 4(0,-3.175)
SOT353_1_1H
  oval 0.3x0.76 smd: 1(-0.65,-0.95) 2(0,-0.95) 3(0.65,-0.95) 4(0.65,0.95) 5(-0.65,0.95)
SW_CK-2
  custom 0.19x0.19 smd: 1(-0.635,-3.81) 2(0.635,-3.81) 3(0.635,3.81) 4(-0.635,3.81)
TDFN10_3M0X3M0X0M8_P0M50_TH
  oval 0.8x0.25 smd: 1(-1.5,1) 2(-1.5,0.5) 3(-1.5,0) 4(-1.5,-0.5) 5(-1.5,-1) 6(1.5,-1) 7(1.5,-0.5) 8(1.5,0) 9(1.5,0.5) 10(1.5,1)
  rect 1.5x2.4 smd: 11(0.01,-0.005)
TDFN14_TH
  oval 0.8x0.2 smd: 1(-1.5,1.2) 2(-1.5,0.8) 3(-1.5,0.4) 4(-1.5,0) 5(-1.5,-0.4) 6(-1.5,-0.8) 7(-1.5,-1.2) 8(1.5,-1.2) 9(1.5,-0.8) 10(1.5,-0.4) 11(1.5,0) 12(1.5,0.4) 13(1.5,0.8) 14(1.5,1.2)
  rect 1.7x2.4 smd: 15(0.01,-0.005)
TP089X043
  round 0.55 smd: 1(0,0)
TS1206
  round 1.8 smd: 1(0,1.448)
unnamed#2
  round 1.194 hole 1.2 unplated: (-3.175,0.254) (3.175,0.254)
  round 0.61 hole 0.61 unplated: (-1.905,0.254) (-0.635,0.254) (0.635,0.254) (1.905,0.254)
unnamed#3
  round 0.635 hole 3.175 unplated: (0,0)
unnamed#4
  round 2.5 hole 2.5 unplated: (-21.6,21.6) (-21.6,-21.6) (21.6,21.6) (21.6,-21.6)
  round 1.651 hole 1.65 unplated: (-19.05,19.05) (19.05,-19.05)
unnamed#5
  round 1.194 hole 1.2 unplated: (-1.905,0.254) (1.905,0.254)
  round 0.61 hole 0.61 unplated: (-0.635,0.254) (0.635,0.254)
unnamed#6
  round 0 smd: (-21.6,-21.6) (21.6,21.6)
VDFN8_THERMAL_1_00H
  oval 0.64x1.9 smd: 1(-1.905,-2.845) 2(-0.635,-2.845) 3(0.635,-2.845) 4(1.905,-2.845) 5(1.905,2.87) 6(0.635,2.87) 7(-0.635,2.87) 8(-1.905,2.87)
  rect 4.1x3.1 smd: 9(0,0)
XTAL_ABLS
  oval 4.57x1.5 smd: 1(-4.318,0) 2(4.318,0)
XTAL_NDK_NX3225DA
  rect 1.4x1.2 smd: 1(-1.1,-0.8) 2(1.1,-0.8) 3(1.1,0.8) 4(-1.1,0.8)

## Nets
+1.8V: B2.1(A) B5.1(A) B6.1(A) B7.1(A) B11.1(A) B12.1(A) B800.1(A) B1500.1(A) B2503.1(A) C143.1(A) C144.1(A) C145.1(A) C146.1(A) C147.1(A) C148.1(A) C149.1(A) C156.1(A) C161.1(A) C162.1(A) C163.1(A) C179.1(A) C180.1(A) C181.1(A) C4020.1(A) R21.1(A) R59.1(A) R72.2(B) R860.2(B) U1.AA20(VDD_CT#1) U1.AA21(VDD_CT#2) U1.AB20(VDD_CT#3) U1.AB21(VDD_CT#4) U1.AB23(PCIE_VDDR#1) U1.AC23(PCIE_VDDR#2) U1.AD17(TSVDD) U1.AD24(PCIE_VDDR#3) U1.AE24(PCIE_VDDR#4) U1.AE25(PCIE_VDDR#5) U1.AE26(PCIE_VDDR#6) U1.AF25(PCIE_VDDR#7) U1.AG26(PCIE_VDDR#8) U1.U12(VDDR4#1) U1.V12(VDDR4#2) U1.Y12(VDDR4#3) UNK+1.8V.1
+1.8V_LDO_EN: MU861.2(EN) Q841.3(C) R862.2(B) U861.2(EN)
+1.8V_LDO_POK: MU861.1(POK) R839.1(A) R863.2(B) U861.1(POK)
+1.8V_LDOOUT: C861.1(A) C862.1(A) C864.1(A) C865.1(A) MU861.6(VOUT) R860.1(A) R865.1(A) U861.6(VOUT)
+1V: B8.1(A) B9.1(A) B801.1(A) B850.1(A) B1502.1(A) B2505.1(A) C150.1(A) C151.1(A) C152.1(A) C153.1(A) C154.1(A) C155.1(A) C158.1(A) MR850.1(A) R8.1(A) R880.2(B) U1.L23(PCIE_VDDC#1) U1.L24(PCIE_VDDC#2) U1.L25(PCIE_VDDC#3) U1.L26(PCIE_VDDC#4) U1.M22(PCIE_VDDC#5) U1.N22(PCIE_VDDC#6) U1.N23(PCIE_VDDC#7) U1.N24(PCIE_VDDC#8) U1.R22(PCIE_VDDC#9) U1.T22(PCIE_VDDC#10) U1.U22(PCIE_VDDC#11) U1.V22(PCIE_VDDC#12) UNK+1V.1
+1V_LDO_EN: R839.2(B) R849.2(B) U851.2(EN)
+1V_LDO_POK: R65.1(A) R859.2(B) U851.1(POK)
+1V_LDOOUT: C851.1(A) C852.1(A) C854.1(A) C855.1(A) R855.1(A) R880.1(A) U851.6(VOUT)
+3.3V_BUS: B71.1(A) B72.1(A) C8.1(A) C27.1(A) C33.1(A) C34.2(B) C35.1(A) C57.1(A) C164.1(A) C165.1(A) C167.1(A) C4001.1(A) C4002.1(A) C4003.1(A) C4013.1(A) C4014.1(A) F2501.1 J4004.8(P8) MPCIE1.A9(+3.3V_A9) MPCIE1.A10(+3.3V_A10) MPCIE1.B8(+3.3V_B8) MR870.1(A) MR871.1(A) MR872.1(A) MR873.1(A) MR4076.1(A) NR4000.2(B) Q1.1(G) Q2.1(G) Q1602.3(C) Q2513.3(C) Q4008.2(E) Q4400.2(E) Q4402.3(C) R1.1(A) R2.1(A) R24.2(B) R33.2(B) R34.2(B) R38.1(A) R43.1(A) R44.1(A) R45.1(A) R46.1(A) R47.1(A) R48.1(A) R49.1(A) R50.1(A) R51.1(A) R52.1(A) R53.1(A) R54.1(A) R55.1(A) R56.1(A) R57.1(A) R58.1(A) R63.2(B) R70.2(B) R71.2(B) R436.1(A) R595.1(A) R849.1(A) R850.1(A) R859.1(A) R862.1(A) R863.1(A) R870.1(A) R871.1(A) R872.1(A) R873.1(A) R1240.2(B) R1241.2(B) R2523.1(A) R4011.1(A) R4017.1(A) R4018.1(A) R4040.1(A) R4050.1(A) R4056.2(B) R4059.2(B) R4075.1(A) R4100.1(A) R4407.1(A) U1.AA17(VDDR3#1) U1.AA18(VDDR3#2) U1.AB17(VDDR3#3) U1.AB18(VDDR3#4) U2.3(WP_N) U2.7(HOLD_N) U2.8(VDD) U4.5(VCC) U4001.2(VDD)
+3.3V_DPB: C2540.1(A) F2501.2 J2501.20(DP_PWR)
+5V: C858.1(A) C868.1(A) MU861.4(CNTL) R856.2(B) R866.1(A) R4413.1(A) U851.4(CNTL) U861.4(CNTL)
+5V_HDMI: C2722.1(A) MJ2501.18 MR2721.2(B) R2701.1(A) R2703.1(A) R2721.2(B)
+5V_VESA: C1624.1(A) C1999.2(B) J1601.14(+5V_POWER) R1005.1(A) R1008.1(A) R2014.1(A) R2721.1(A) R4412.1(A) U1999.14(VCC)
+5V_VESA2: MR2014.1(A) MR2721.1(A) R4411.1(A)
+5V_VGAH: C1010.1(A) C1011.1(A) MJ1001.9(NC) MR2014.2(B) R2005.1(A) R2008.1(A) R2014.2(B)
+12V_BUS: B702.2(B) B4001.1(A) C14.1(A) C20.1(A) C21.1(A) C43.1(A) C44.1(A) C47.1(A) C410.1 C606.1(A) C609.1(A) C706.1(A) D601.2(A) D701.2(A) L611.1(A) MPCIE1.A2(+12V_A2) MPCIE1.A3(+12V_A3) MPCIE1.B1(+12V_B1) MPCIE1.B2(+12V_B2) MPCIE1.B3(+12V_B3) R607.1(A) R608.2(B) R616.2(B) R702.2(B) R707.1(A) R843.2(B) R844.1(A) R852.2(B) R857.1(A) R1804.1(A) R1805.1(A) R4055.2(B) R4102.1(A) R4105.1(A) R4112.1(A) U403.1(IN)
+AVDD: B2.2(B) C1054.1(A) C1055.1(A) U1.AG24(AVDD)
+VCCT_DAC: C4070.1(A) C4071.1(A) R4075.2(B) U4050.13(VCC)
+VDD1DI: B6.2(B) C1050.1(A) C1051.1(A) C1052.1(A) U1.AE23(VDD1DI)
+VDDC: B850.2(B) C85.1(A) C86.1(A) C87.1(A) C168.1(A) C169.1(A) C170.1(A) C171.1(A) C172.1(A) C173.1(A) C174.1(A) C175.1(A) C176.1(A) C177.1(A) C182.1(A) C183.1(A) C184.1(A) C185.1(A) C186.1(A) C187.1(A) C188.1(A) C189.1(A) C190.1(A) C193.1(A) C194.1(A) C195.1(A) C196.1(A) C623.1(A) C624.1(A) C625.1(P) C626.1(P) C629.1(A) C630.1(A) L601.2 MB9.1(A) MC174.1(A) MC175.1(A) MC176.1(A) MC177.1(A) MC196.1(A) MR850.2(B) NS600.1(N1) R841.1(A) U1.AA15(VDDC#21) U1.M11(NC#M11) U1.M12(NC#M12) U1.M13(VDDCI#1) U1.M15(VDDCI#2) U1.M16(VDDCI#3) U1.M17(VDDCI#4) U1.M18(VDDCI#5) U1.M20(VDDCI#6) U1.M21(VDDCI#7) U1.N15(VDDC#1) U1.N17(VDDC#2) U1.N20(VDDCI#8) U1.R13(VDDC#3) U1.R16(VDDC#4) U1.R18(VDDC#5) U1.R21(BIF_VDDC#21) U1.T12(VDDC#7) U1.T15(VDDC#8) U1.T17(VDDC#9) U1.T20(VDDC#10) U1.U13(VDDC#11) U1.U16(VDDC#12) U1.U18(VDDC#13) U1.U21(BIF_VDDC#22) U1.V15(VDDC#15) U1.V17(VDDC#16) U1.V20(VDDC#17) U1.V21(VDDC#6) U1.Y13(VDDC#18) U1.Y16(VDDC#19) U1.Y18(VDDC#20) U1.Y21(VDDC#14) VDDC.1
+VDDC_SOURCE: C615.1(A) C616.1(A) C617.1(A) C619.1(A) C620.1(A) C621.1(A) C631.1(P) C633.1(A) L611.2(B) Q601.5(D5) Q601.6(D6) Q601.7(D7) Q601.8(D8) Q601.9(D9) R608.1(A) R616.1(A)
